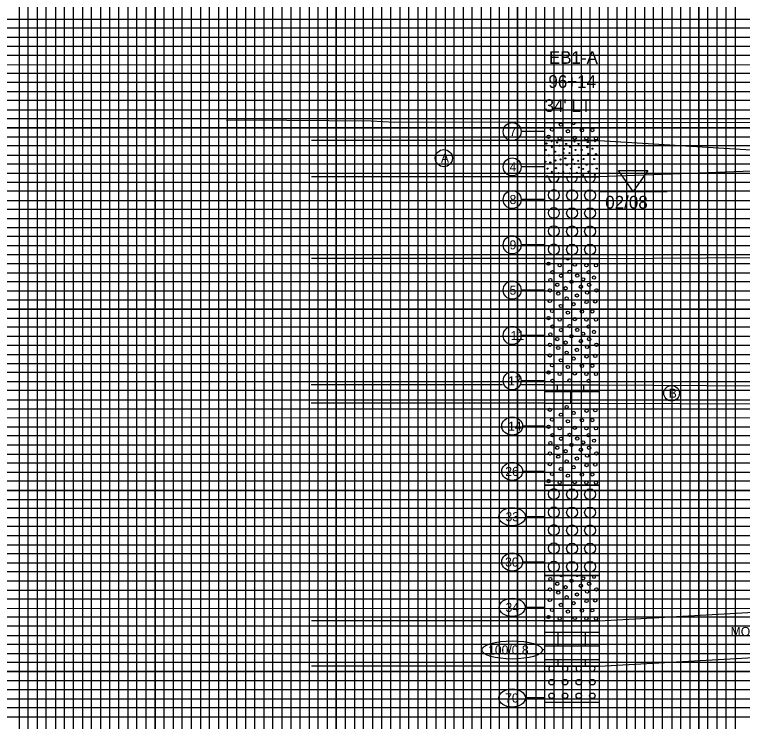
# Model space of a CAD drawing. Extents: x -13 to 886, y -5 to 434.
# Drawn here: x 626.7 to 707.1, y 245.4 to 323.4 of the extents above; entities that cross this region are included whole.
import ezdxf

# ---------------------------------------------------------------- set-up
doc = ezdxf.new("R2010")
doc.units = 0
for name, color, linetype in [('Default', 7, 'Continuous'), ('Exist XS Ground Line', 7, 'Continuous'), ('Prop Road Sect_ Boring - Header Labels from Geopak', 7, 'Continuous'), ('Prop Road Sect_ Boring - Material (Outline)', 7, 'Continuous'), ('Prop Road Sect_ Boring - Peripheral (24 Hr GrdWtr Date)', 7, 'Continuous'), ('Prop Road Sect_ Boring - Peripheral (SPT Oval + Leader)', 7, 'Continuous'), ('Prop Road Sect_ Boring - Peripheral (SPT Tx)', 7, 'Continuous'), ('Prop Road Sect_ Material - Contact (General - Minor)', 7, 'Continuous'), ('Prop Road Sect_ Material - Tx (Composite Desc)', 7, 'Continuous'), ('Sheet Cross Section Grid Major CELL', 7, 'Continuous'), ('Sheet Cross Section Grid Middle CELL', 7, 'Continuous'), ('Sheet Cross Section Grid Minor 1 CELL', 7, 'Continuous'), ('Sheet Cross Section Grid Minor 2 CELL', 7, 'Continuous'), ('Sheet DOT Grid CELL', 7, 'Continuous'), ('Water Mark (24 Hr) Cell', 7, 'Continuous')]:
    doc.layers.add(name, color=color, linetype=linetype)

msp = doc.modelspace()

# ---------------------------------------------------------------- linework, layer by layer
at = {"layer": 'Default'}
for p, q in [((685.23, 282.545), (691.301, 282.545)), ((685.23, 280.521), (691.301, 280.521)), ((688.237, 255.236), (688.237, 256.49)), ((685.243, 255.236), (691.237, 255.236)), ((686.737, 253.738), (686.737, 255.236)), ((689.737, 253.738), (689.737, 255.236)), ((691.24, 255.236), (691.243, 255.236)), ((685.243, 253.738), (691.237, 253.738)), ((688.237, 252.239), (688.237, 253.738)), ((691.24, 253.738), (691.243, 253.738)), ((685.243, 252.239), (691.237, 252.239)), ((686.737, 251.49), (686.737, 252.239)), ((689.737, 251.49), (689.737, 252.239)), ((691.24, 252.239), (691.243, 252.239))]:
    msp.add_line(p, q, dxfattribs=at)
for centre, radius in [((685.417, 309.177), 0.06), ((686.617, 309.285), 0.06), ((688.522, 309.393), 0.06), ((689.995, 309.339), 0.06), ((685.363, 308.469), 0.06), ((686.017, 308.769), 0.06), ((686.863, 308.931), 0.06), ((687.352, 308.577), 0.06), ((687.598, 309.123), 0.06), ((688.06, 308.796), 0.06), ((688.633, 308.469), 0.06), ((688.96, 309.123), 0.06), ((689.314, 308.469), 0.06), ((689.938, 308.769), 0.06), ((690.511, 308.604), 0.06), ((685.69, 307.869), 0.06), ((686.371, 308.277), 0.06), ((686.806, 307.869), 0.06), ((687.298, 308.115), 0.06), ((687.514, 307.542), 0.06), ((687.979, 308.115), 0.06), ((688.876, 307.896), 0.06), ((690.022, 308.031), 0.06), ((690.892, 308.004), 0.06), ((685.309, 307.161), 0.06), ((685.855, 307.08), 0.06), ((686.425, 307.296), 0.06), ((686.971, 307.407), 0.06), ((686.971, 306.888), 0.06), ((687.679, 306.807), 0.06), ((688.333, 307.407), 0.06), ((688.522, 306.915), 0.06), ((688.93, 307.269), 0.06), ((689.503, 307.461), 0.06), ((689.857, 306.834), 0.06), ((690.484, 306.888), 0.06), ((690.703, 307.461), 0.06), ((685.555, 306.399), 0.06), ((686.017, 306.045), 0.06), ((686.482, 306.453), 0.06), ((687.271, 306.045), 0.06), ((688.141, 306.399), 0.06), ((688.768, 305.934), 0.06), ((688.987, 306.534), 0.06), ((689.476, 306.372), 0.06), ((690.076, 306.072), 0.06), ((690.968, 306.41), 0.06), ((685.501, 305.562), 0.06), ((686.752, 305.898), 0.06), ((687.979, 305.88), 0.06), ((689.476, 305.691), 0.06), ((690.757, 305.718), 0.06), ((686.241, 303.487), 0.6), ((688.251, 303.463), 0.6), ((690.237, 303.463), 0.6), ((686.241, 301.519), 0.6), ((690.237, 301.489), 0.6), ((686.241, 299.503), 0.6), ((690.237, 299.479), 0.6), ((686.241, 297.493), 0.6), ((690.237, 297.469), 0.6), ((685.664, 295.912), 0.18), ((686.888, 295.747), 0.18), ((688.55, 295.801), 0.18), ((689.831, 295.747), 0.18), ((690.893, 295.747), 0.18), ((686.082, 294.973), 0.18), ((687.038, 294.584), 0.18), ((687.973, 295.02), 0.18), ((688.82, 294.605), 0.18), ((690.082, 294.973), 0.18), ((685.856, 294.106), 0.18), ((688.183, 293.909), 0.18), ((689.477, 294.187), 0.18), ((690.674, 294.379), 0.18), ((685.802, 292.963), 0.18), ((686.618, 293.59), 0.18), ((687.542, 293.209), 0.18), ((689.231, 293.371), 0.18), ((690.131, 293.59), 0.18), ((690.947, 292.963), 0.18), ((686.726, 292.609), 0.18), ((688.784, 292.402), 0.18), ((689.912, 292.717), 0.18), ((685.802, 291.793), 0.18), ((687.656, 292.093), 0.18), ((688.43, 291.445), 0.18), ((689.858, 291.682), 0.18), ((690.812, 291.739), 0.18), ((686.045, 290.701), 0.18), ((687.026, 291.247), 0.18), ((689.339, 290.632), 0.18), ((690.485, 290.65), 0.18), ((685.664, 289.915), 0.18), ((686.888, 289.75), 0.18), ((687.788, 290.512), 0.18), ((688.55, 289.804), 0.18), ((689.831, 289.75), 0.18), ((690.893, 289.75), 0.18), ((686.082, 288.976), 0.18), ((687.973, 289.023), 0.18), ((690.082, 288.976), 0.18), ((687.038, 288.587), 0.18), ((688.82, 288.608), 0.18), ((689.477, 288.19), 0.18), ((690.674, 288.382), 0.18), ((685.856, 288.109), 0.18), ((688.183, 287.912), 0.18), ((689.231, 287.374), 0.18), ((690.131, 287.593), 0.18), ((685.802, 286.966), 0.18), ((686.726, 286.612), 0.18), ((687.542, 287.212), 0.18), ((689.912, 286.72), 0.18), ((690.947, 286.966), 0.18), ((685.802, 285.796), 0.18), ((687.656, 286.096), 0.18), ((688.784, 286.405), 0.18), ((690.812, 285.742), 0.18), ((687.026, 285.25), 0.18), ((688.43, 285.448), 0.18), ((689.858, 285.685), 0.18), ((686.045, 284.704), 0.18), ((687.788, 284.515), 0.18), ((689.339, 284.635), 0.18), ((690.485, 284.653), 0.18), ((685.664, 283.918), 0.18), ((686.888, 283.753), 0.18), ((688.55, 283.807), 0.18), ((689.831, 283.753), 0.18), ((690.893, 283.753), 0.18), ((686.082, 282.979), 0.18), ((687.973, 283.026), 0.18), ((690.082, 282.979), 0.18), ((687.656, 280.099), 0.18), ((685.802, 279.799), 0.18), ((688.43, 279.451), 0.18), ((689.858, 279.688), 0.18), ((690.812, 279.745), 0.18), ((686.045, 278.707), 0.18), ((687.026, 279.253), 0.18), ((687.788, 278.518), 0.18), ((689.339, 278.638), 0.18), ((690.485, 278.656), 0.18), ((685.664, 277.921), 0.18), ((686.888, 277.756), 0.18), ((688.55, 277.81), 0.18), ((689.831, 277.756), 0.18), ((690.893, 277.756), 0.18), ((686.082, 276.982), 0.18), ((687.973, 277.029), 0.18), ((690.082, 276.982), 0.18), ((685.856, 276.115), 0.18), ((687.038, 276.593), 0.18), ((688.82, 276.614), 0.18), ((689.477, 276.196), 0.18), ((690.674, 276.388), 0.18), ((686.618, 275.599), 0.18), ((688.183, 275.918), 0.18), ((689.231, 275.38), 0.18), ((690.131, 275.599), 0.18), ((685.802, 274.972), 0.18), ((686.726, 274.618), 0.18), ((687.542, 275.218), 0.18), ((689.912, 274.726), 0.18), ((690.947, 274.972), 0.18), ((685.802, 273.802), 0.18), ((687.656, 274.102), 0.18), ((688.784, 274.411), 0.18), ((689.858, 273.691), 0.18), ((690.812, 273.748), 0.18), ((687.026, 273.256), 0.18), ((688.43, 273.454), 0.18), ((686.045, 272.71), 0.18), ((687.788, 272.521), 0.18), ((689.339, 272.641), 0.18), ((690.485, 272.659), 0.18), ((685.664, 271.924), 0.18), ((686.888, 271.759), 0.18), ((688.55, 271.813), 0.18), ((689.831, 271.759), 0.18), ((690.893, 271.759), 0.18), ((686.241, 270.497), 0.6), ((688.251, 270.473), 0.6), ((690.237, 270.473), 0.6), ((686.241, 268.487), 0.6), ((688.251, 268.463), 0.6), ((690.237, 268.463), 0.6), ((686.241, 266.519), 0.6), ((688.251, 266.489), 0.6), ((690.237, 266.489), 0.6), ((686.241, 264.503), 0.6), ((688.251, 264.479), 0.6), ((690.237, 264.479), 0.6), ((686.241, 262.493), 0.6), ((688.251, 262.469), 0.6), ((690.237, 262.469), 0.6), ((685.856, 261.115), 0.18), ((688.183, 260.918), 0.18), ((689.477, 261.196), 0.18), ((686.618, 260.599), 0.18), ((687.542, 260.218), 0.18), ((689.231, 260.38), 0.18), ((690.131, 260.599), 0.18), ((685.802, 259.972), 0.18), ((686.726, 259.618), 0.18), ((688.784, 259.411), 0.18), ((689.912, 259.726), 0.18), ((690.947, 259.972), 0.18), ((685.802, 258.802), 0.18), ((687.656, 259.102), 0.18), ((688.43, 258.454), 0.18), ((689.858, 258.691), 0.18), ((690.812, 258.748), 0.18), ((686.045, 257.71), 0.18), ((687.026, 258.256), 0.18), ((689.339, 257.641), 0.18), ((690.485, 257.659), 0.18), ((685.664, 256.924), 0.18), ((687.788, 257.521), 0.18), ((688.55, 256.813), 0.18), ((686.888, 256.759), 0.18), ((689.831, 256.759), 0.18), ((690.893, 256.759), 0.18), ((685.99, 249.736), 0.3), ((687.49, 249.736), 0.3), ((688.99, 249.736), 0.3), ((690.49, 249.736), 0.3), ((685.99, 248.236), 0.3), ((687.49, 248.236), 0.3), ((688.99, 248.236), 0.3), ((690.49, 248.236), 0.3)]:
    msp.add_circle(centre, radius, dxfattribs=at)
for centre, radius, start, end in [((685.99, 309.447), 0.06, 134.14919, 45.85081), ((690.784, 309.447), 0.06, 134.14919, 45.85081), ((686.241, 305.497), 0.6, 180.65482, 359.34518), ((688.251, 305.473), 0.6, 178.36275, 1.63725), ((690.237, 305.473), 0.6, 178.36275, 1.63725), ((687.788, 296.509), 0.18, 185.82425, 354.17575), ((689.339, 296.629), 0.18, 230.18751, 309.81249), ((690.485, 296.647), 0.18, 240.24367, 299.75633), ((687.038, 261.593), 0.18, 214.64743, 325.35257), ((688.82, 261.614), 0.18, 223.34627, 316.65373), ((690.674, 261.388), 0.18, 145.2009, 34.7991), ((685.99, 251.236), 0.3, 121.90898, 58.09102), ((687.49, 251.236), 0.3, 121.90898, 58.09102), ((688.99, 251.236), 0.3, 121.90898, 58.09102), ((690.49, 251.236), 0.3, 121.90898, 58.09102)]:
    msp.add_arc(centre, radius, start, end, dxfattribs=at)
at = {"layer": 'Exist XS Ground Line'}
msp.add_lwpolyline([(650.115, 311.763), (652.113, 311.781), (666.089, 311.684), (668.65, 311.535), (672.715, 311.547), (682.507, 311.512), (686.055, 311.503), (690.603, 311.476), (715.981, 311.545), (717.469, 311.623), (722.243, 311.635), (730.438, 311.655), (734.382, 311.675), (760.339, 311.838), (767.402, 311.852), (778.837, 311.921), (784.232, 311.947)], dxfattribs=at)
at = {"layer": 'Prop Road Sect_ Boring - Material (Outline)'}
for points in [[(685.243, 311.49), (691.243, 311.49), (691.243, 309.49), (685.243, 309.49)], [(685.243, 309.49), (691.243, 309.49), (691.243, 305.49), (685.243, 305.49)], [(685.243, 305.49), (691.243, 305.49), (691.243, 296.49), (685.243, 296.49)], [(685.243, 296.49), (691.243, 296.49), (691.243, 271.49), (685.243, 271.49)], [(685.243, 271.49), (691.243, 271.49), (691.243, 261.49), (685.243, 261.49)], [(685.243, 261.49), (691.243, 261.49), (691.243, 256.49), (685.243, 256.49)], [(685.243, 256.49), (691.243, 256.49), (691.243, 251.49), (685.243, 251.49)], [(685.243, 251.49), (691.243, 251.49), (691.243, 247.49), (685.243, 247.49)]]:
    msp.add_lwpolyline(points, close=True, dxfattribs=at)
for centre, radius in [((686.045, 310.71), 0.18), ((687.026, 311.256), 0.18), ((689.339, 310.641), 0.18), ((690.485, 310.659), 0.18), ((685.664, 309.924), 0.18), ((687.788, 310.521), 0.18), ((688.55, 309.813), 0.18), ((686.888, 309.759), 0.18), ((689.831, 309.759), 0.18), ((690.893, 309.759), 0.18), ((688.251, 301.489), 0.6), ((688.251, 299.479), 0.6), ((688.251, 297.469), 0.6), ((686.618, 287.593), 0.18)]:
    msp.add_circle(centre, radius, dxfattribs=at)
msp.add_arc((688.43, 311.454), 0.18, 168.2251, 11.7749, dxfattribs=at)
at = {"layer": 'Prop Road Sect_ Boring - Peripheral (SPT Oval + Leader)'}
for p, q in [((685.243, 310.49), (682.626, 310.49)), ((685.243, 306.59), (682.626, 306.59)), ((685.243, 302.99), (682.626, 302.99)), ((685.243, 297.99), (682.626, 297.99)), ((685.243, 292.99), (682.626, 292.99)), ((685.243, 287.99), (682.626, 287.99)), ((685.243, 282.99), (682.626, 282.99)), ((686.662, 281.824), (686.662, 282.542)), ((689.537, 281.824), (689.537, 282.542)), ((685.23, 281.824), (690.974, 281.824)), ((688.099, 280.521), (688.099, 281.824)), ((690.977, 281.824), (691.247, 281.824)), ((685.243, 277.99), (682.792, 277.99)), ((685.243, 272.99), (682.792, 272.99)), ((685.243, 267.99), (683.115, 267.99)), ((685.243, 262.99), (682.792, 262.99)), ((685.243, 257.99), (683.075, 257.99)), ((685.243, 253.288), (684.989, 253.288)), ((685.243, 247.99), (683.099, 247.99))]:
    msp.add_line(p, q, dxfattribs=at)
for centre, major_axis, ratio in [((681.643, 310.49), (0, 1), 0.983465), ((681.643, 306.59), (0, 1), 0.983465), ((681.643, 302.99), (0, 1), 0.983465), ((681.643, 297.99), (0, 1), 0.983465), ((681.643, 292.99), (0, 1), 0.983465), ((681.643, 287.99), (0, 1), 0.983465), ((681.643, 282.99), (0, 1), 0.983465), ((681.643, 277.99), (1.149, 0), 0.870459), ((681.643, 272.99), (1.149, 0), 0.870459), ((681.643, 267.99), (1.472, 0), 0.679508), ((681.643, 262.99), (1.149, 0), 0.870459), ((681.643, 257.99), (1.432, 0), 0.698186), ((681.643, 253.288), (3.346, 0), 0.298894), ((681.643, 247.99), (1.456, 0), 0.686858)]:
    msp.add_ellipse(centre, major_axis=major_axis, ratio=ratio, dxfattribs=at)
at = {"layer": 'Prop Road Sect_ Material - Contact (General - Minor)'}
for p, q in [((685.243, 309.49), (659.489, 309.49)), ((685.243, 305.49), (659.489, 305.49)), ((685.243, 296.49), (659.489, 296.49)), ((691.243, 296.49), (788.243, 297.077)), ((680.581, 282.545), (659.476, 282.545)), ((685.23, 282.545), (682.616, 282.545)), ((691.301, 282.545), (788.25, 281.97)), ((685.23, 280.521), (659.476, 280.521)), ((691.301, 280.521), (788.25, 280.171)), ((691.243, 256.49), (788.243, 262.077)), ((691.243, 251.49), (788.243, 257.077)), ((685.243, 256.49), (659.489, 256.49)), ((685.243, 251.49), (659.489, 251.49))]:
    msp.add_line(p, q, dxfattribs=at)
msp.add_lwpolyline([(691.243, 309.49), (731.963, 307.005), (691.243, 305.49)], dxfattribs=at)
at = {"layer": 'Prop Road Sect_ Material - Tx (Composite Desc)'}
for centre, radius in [((674.106, 307.561), 0.946), ((699.229, 281.623), 0.86)]:
    msp.add_circle(centre, radius, dxfattribs=at)
at = {"layer": 'Sheet Cross Section Grid Major CELL'}
for p, q in [((632.243, 200.903), (632.243, 410.903)), ((642.243, 410.903), (642.243, 200.903)), ((652.243, 200.903), (652.243, 410.903)), ((662.243, 410.903), (662.243, 200.903)), ((672.243, 200.903), (672.243, 410.903)), ((682.243, 410.903), (682.243, 200.903)), ((692.243, 200.903), (692.243, 410.903)), ((702.243, 410.903), (702.243, 200.903))]:
    msp.add_line(p, q, dxfattribs=at)
for points in [[(562.243, 320.903), (882.243, 320.903), (882.243, 310.903), (562.243, 310.903)], [(562.243, 300.903), (882.243, 300.903), (882.243, 290.903), (562.243, 290.903)], [(562.243, 280.903), (882.243, 280.903), (882.243, 270.903), (562.243, 270.903)], [(562.243, 260.903), (882.243, 260.903), (882.243, 250.903), (562.243, 250.903)]]:
    msp.add_lwpolyline(points, dxfattribs=at)
at = {"layer": 'Sheet Cross Section Grid Middle CELL'}
for points in [[(627.243, 410.903), (627.243, 200.903), (637.243, 200.903), (637.243, 410.903)], [(647.243, 410.903), (647.243, 200.903), (657.243, 200.903), (657.243, 410.903)], [(667.243, 410.903), (667.243, 200.903), (677.243, 200.903), (677.243, 410.903)], [(687.243, 410.903), (687.243, 200.903), (697.243, 200.903), (697.243, 410.903)], [(562.243, 305.903), (882.243, 305.903), (882.243, 315.903), (562.243, 315.903)], [(562.243, 285.903), (882.243, 285.903), (882.243, 295.903), (562.243, 295.903)], [(562.243, 265.903), (882.243, 265.903), (882.243, 275.903), (562.243, 275.903)], [(562.243, 245.903), (882.243, 245.903), (882.243, 255.903), (562.243, 255.903)]]:
    msp.add_lwpolyline(points, dxfattribs=at)
at = {"layer": 'Sheet Cross Section Grid Minor 1 CELL'}
for points in [[(562.243, 322.903), (882.243, 322.903), (882.243, 321.903), (562.243, 321.903)], [(562.243, 319.903), (882.243, 319.903), (882.243, 318.903), (562.243, 318.903)], [(562.243, 317.893), (882.313, 317.813), (882.243, 316.903), (562.243, 316.903)], [(562.243, 314.903), (882.243, 314.903), (882.243, 313.903), (562.243, 313.903)], [(562.243, 312.903), (882.243, 312.903), (882.243, 311.903), (562.243, 311.903)], [(562.243, 309.903), (882.243, 309.903), (882.243, 308.903), (562.243, 308.903)], [(562.243, 307.903), (882.243, 307.903), (882.243, 306.903), (562.243, 306.903)], [(562.243, 304.903), (882.243, 304.903), (882.243, 303.903), (562.243, 303.903)], [(562.243, 302.903), (882.243, 302.903), (882.243, 301.903), (562.243, 301.903)], [(562.243, 299.903), (882.243, 299.903), (882.243, 298.903), (562.243, 298.903)], [(562.243, 297.903), (882.243, 297.903), (882.243, 296.903), (562.243, 296.903)], [(562.243, 294.903), (882.243, 294.903), (882.243, 293.903), (562.243, 293.903)], [(562.243, 292.903), (882.243, 292.903), (882.243, 291.903), (562.243, 291.903)], [(562.243, 289.903), (882.243, 289.903), (882.243, 288.903), (562.243, 288.903)], [(562.243, 287.903), (882.243, 287.903), (882.243, 286.903), (562.243, 286.903)], [(562.243, 284.903), (882.243, 284.903), (882.243, 283.903), (562.243, 283.903)], [(562.243, 282.903), (882.243, 282.903), (882.243, 281.903), (562.243, 281.903)], [(562.243, 279.903), (882.243, 279.903), (882.233, 278.883), (562.243, 278.903)], [(562.243, 277.903), (882.243, 277.903), (882.243, 276.903), (562.243, 276.903)], [(562.243, 274.903), (882.243, 274.903), (882.243, 273.903), (562.243, 273.903)], [(562.243, 272.903), (882.243, 272.903), (882.243, 271.903), (562.243, 271.903)], [(562.243, 269.903), (882.243, 269.903), (882.243, 268.903), (562.243, 268.903)], [(562.243, 267.903), (882.243, 267.903), (882.243, 266.903), (562.243, 266.903)], [(562.243, 264.903), (882.243, 264.903), (882.243, 263.903), (562.243, 263.903)], [(562.243, 262.903), (882.243, 262.903), (882.243, 261.903), (562.243, 261.903)], [(562.243, 259.903), (882.243, 259.903), (882.243, 258.903), (562.243, 258.903)], [(562.243, 257.893), (882.313, 257.813), (882.243, 256.903), (562.243, 256.903)], [(562.243, 254.903), (882.243, 254.903), (882.243, 253.903), (562.243, 253.903)], [(562.243, 252.903), (882.243, 252.903), (882.243, 251.903), (562.243, 251.903)], [(562.243, 249.903), (882.243, 249.903), (882.243, 248.903), (562.243, 248.903)], [(562.243, 247.903), (882.243, 247.903), (882.243, 246.903), (562.243, 246.903)]]:
    msp.add_lwpolyline(points, dxfattribs=at)
at = {"layer": 'Sheet Cross Section Grid Minor 2 CELL'}
for points in [[(627.243, 200.903), (628.243, 200.903), (628.243, 410.903), (629.243, 410.903), (629.243, 200.903)], [(629.243, 200.903), (630.243, 200.903), (630.243, 410.903), (631.243, 410.903), (631.243, 200.903)], [(632.243, 200.903), (633.243, 200.903), (633.243, 410.903), (634.243, 410.903), (634.243, 200.903)], [(634.243, 200.903), (635.243, 200.903), (635.243, 410.903), (636.243, 410.903), (636.243, 200.903)], [(637.243, 200.903), (638.243, 200.903), (638.243, 410.903), (639.243, 410.903), (639.243, 200.903)], [(639.243, 200.903), (640.243, 200.903), (640.243, 410.903), (641.243, 410.903), (641.243, 200.903)], [(642.243, 200.903), (643.243, 200.903), (643.243, 410.903), (644.243, 410.903), (644.243, 200.903)], [(644.243, 200.903), (645.243, 200.903), (645.243, 410.903), (646.243, 410.903), (646.243, 200.903)], [(647.243, 200.903), (648.243, 200.903), (648.243, 410.903), (649.243, 410.903), (649.243, 200.903)], [(649.243, 200.903), (650.243, 200.903), (650.243, 410.903), (651.243, 410.903), (651.243, 200.903)], [(652.243, 200.903), (653.243, 200.903), (653.243, 410.903), (654.243, 410.903), (654.243, 200.903)], [(654.243, 200.903), (655.243, 200.903), (655.243, 410.903), (656.243, 410.903), (656.243, 200.903)], [(657.243, 200.903), (658.243, 200.903), (658.243, 410.903), (659.243, 410.903), (659.243, 200.903)], [(659.243, 200.903), (660.243, 200.903), (660.243, 410.903), (661.243, 410.903), (661.243, 200.903)], [(662.243, 200.903), (663.243, 200.903), (663.243, 410.903), (664.243, 410.903), (664.243, 200.903)], [(664.243, 200.903), (665.243, 200.903), (665.243, 410.903), (666.243, 410.903), (666.243, 200.903)], [(667.243, 200.903), (668.243, 200.903), (668.243, 410.903), (669.243, 410.903), (669.243, 200.903)], [(669.243, 200.903), (670.243, 200.903), (670.243, 410.903), (671.243, 410.903), (671.243, 200.903)], [(672.243, 200.903), (673.243, 200.903), (673.243, 410.903), (674.243, 410.903), (674.243, 200.903)], [(674.243, 200.903), (675.243, 200.903), (675.243, 410.903), (676.243, 410.903), (676.243, 200.903)], [(677.243, 200.903), (678.243, 200.903), (678.243, 410.903), (679.243, 410.903), (679.243, 200.903)], [(679.243, 200.903), (680.243, 200.903), (680.243, 410.903), (681.243, 410.903), (681.243, 200.903)], [(682.243, 200.903), (683.243, 200.903), (683.243, 410.903), (684.243, 410.903), (684.243, 200.903)], [(684.243, 200.903), (685.243, 200.903), (685.243, 410.903), (686.243, 410.903), (686.243, 200.903)], [(687.243, 200.903), (688.243, 200.903), (688.243, 410.903), (689.243, 410.903), (689.243, 200.903)], [(689.243, 200.903), (690.243, 200.903), (690.243, 410.903), (691.243, 410.903), (691.243, 200.903)], [(692.243, 200.903), (693.243, 200.903), (693.243, 410.903), (694.243, 410.903), (694.243, 200.903)], [(694.243, 200.903), (695.243, 200.903), (695.243, 410.903), (696.243, 410.903), (696.243, 200.903)], [(697.243, 200.903), (698.243, 200.903), (698.243, 410.903), (699.243, 410.903), (699.243, 200.903)], [(699.243, 200.903), (700.243, 200.903), (700.243, 410.903), (701.243, 410.903), (701.243, 200.903)], [(702.243, 200.903), (703.243, 200.903), (703.243, 410.903), (704.243, 410.903), (704.243, 200.903)], [(704.243, 200.903), (705.243, 200.903), (705.243, 410.903), (706.243, 410.903), (706.243, 200.903)]]:
    msp.add_lwpolyline(points, dxfattribs=at)
at = {"layer": 'Sheet DOT Grid CELL'}
for p, q in [((632.243, 200.903), (632.243, 410.903)), ((642.243, 200.903), (642.243, 410.903)), ((652.243, 200.903), (652.243, 410.903)), ((662.243, 200.903), (662.243, 410.903)), ((672.243, 200.903), (672.243, 410.903)), ((682.243, 200.903), (682.243, 410.903)), ((692.243, 200.903), (692.243, 410.903)), ((702.243, 200.903), (702.243, 410.903)), ((562.243, 320.903), (882.243, 320.903)), ((562.243, 310.903), (882.243, 310.903)), ((562.243, 300.903), (882.243, 300.903)), ((562.243, 290.903), (882.243, 290.903)), ((562.243, 280.903), (882.243, 280.903)), ((562.243, 270.903), (882.243, 270.903)), ((562.243, 260.903), (882.243, 260.903)), ((562.243, 250.903), (882.243, 250.903))]:
    msp.add_line(p, q, dxfattribs=at)
at = {"layer": 'Water Mark (24 Hr) Cell'}
for p, q in [((691.243, 303.89), (694.993, 303.89)), ((694.993, 303.89), (698.743, 303.89))]:
    msp.add_line(p, q, dxfattribs=at)
msp.add_lwpolyline([(693.38, 306.197), (696.605, 306.197), (694.993, 303.89)], close=True, dxfattribs=at)

# ---------------------------------------------------------------- texts
at = {"layer": 'Prop Road Sect_ Boring - Header Labels from Geopak'}
for s, p in [('EB1-A', (685.696, 317.962)), ('96+14', (685.641, 315.312)), ("34' LT", (685.222, 312.662))]:
    msp.add_text(s, height=1.4, dxfattribs=at).set_placement(p)
at = {"layer": 'Prop Road Sect_ Boring - Peripheral (24 Hr GrdWtr Date)'}
msp.add_text('02/08', height=1.4, dxfattribs=at).set_placement((691.917, 301.992))
at = {"layer": 'Prop Road Sect_ Boring - Peripheral (SPT Tx)'}
for s, p in [('7', (681.359, 309.99)), ('4', (681.359, 306.09)), ('8', (681.359, 302.49)), ('9', (681.359, 297.49)), ('5', (681.359, 292.49)), ('11', (681.478, 287.49)), ('17', (681.194, 282.49)), ('14', (681.194, 277.49)), ('26', (680.887, 272.49)), ('33', (680.911, 267.49)), ('30', (680.871, 262.49)), ('34', (680.911, 257.49)), ('100/0.8', (678.997, 252.788)), ('70', (680.871, 247.49))]:
    msp.add_text(s, height=1, dxfattribs=at).set_placement(p)
at = {"layer": 'Prop Road Sect_ Material - Tx (Composite Desc)'}
for s, p in [('A', (673.784, 307.061)), ('B', (698.922, 281.123)), ('MODERATELY HARD', (705.75, 254.829))]:
    msp.add_text(s, height=1, dxfattribs=at).set_placement(p)

doc.saveas('drawing.dxf')
